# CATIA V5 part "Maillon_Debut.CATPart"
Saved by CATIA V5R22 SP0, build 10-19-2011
Part number: Maillon_debut
Bounding box of the stored display mesh (mm): x -0.4 to 26.6, y -32.303 to 16.847, z -12 to 12
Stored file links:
  C:\Users\achbo\Desktop\BOUCHEMAMA_Achraf_P1-1_Chaine Porte Cables\Maillon_Debut.CATPart
  C:\Program Files\Dassault Systemes\B22\win_b64\startup\materials\French\Catalog.CATMaterial
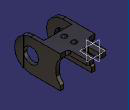
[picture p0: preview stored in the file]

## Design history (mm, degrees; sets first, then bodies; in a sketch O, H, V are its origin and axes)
Body1 (main body), material "Acier"
  Sketch1 on yz-plane, origin (0, 0, 0), H (0, 1, 0), V (0, 0, 1)
    point P1 (1.8468, 12)
    line L1 (1.8468, 12) -> (-20.3032, 12)
    point P2 (-20.3032, 12)
    axis line L2 (84.3362, 0) -> (-201.4699, 0)
    point P3 (84.3362, 0)
    arc A1 centre (-20.3032, 0) radius 12 from (-20.3032, 12) to (-32.3032, 0) ccw
    point P5 (-20.3032, 0)
    point P6 (-32.3032, 0)
    point P7 (-20.3032, -12)
    point P8 (1.8468, -12)
    line L3 (1.8468, -12) -> (-20.3032, -12)
    point P9 (-32.3032, 0)
    arc A2 centre (-20.3032, 0) radius 12 from (-20.3032, -12) to (-32.3032, 0) cw
    line L4 (1.8468, 12) -> (1.8468, 8.802)
    point P11 (1.8468, 8.802)
    point P12 (1.8468, -8.802)
    point P13 (1.8468, -12)
    line L5 (1.8468, -12) -> (1.8468, -8.802)
    arc A3 centre (10.7223, 0) radius 12.5 from (1.8468, 8.802) to (1.8468, -8.802) ccw
    point P15 (0, 6.4251)
    length L1 = 22.15
    radius A1 = 12
    length L4 = 3.198
    radius A3 = 12.5
    horizontal: L1 H, L2 H
    coincidence: P3 H, P5 L2, P6 L2, A3 P15, P15 V, P6 P9, P8 P13
    symmetry: P2 P7 L2, P1 P8 L2, L1 L3 L2, P6 P9 L2, A1 A2 L2, P11 P12 L2, P1 P13 L2, L4 L5 L2
    vertical: L4 V
  Pad1: profile Sketch1, direction (1, 0, 0), length 26.2
  Sketch2 on end face of Pad1, origin (26.2, -24.6429, -1.8283), H (0, 1, 0), V (0, 0, 1)
    point P1 (4.3397, 1.8283)
    reference projected arc E1 centre (4.3397, 1.8283) radius 12 from (4.3397, 13.8283) to (-7.6603, 1.8283) ccw from edge [face of Pad1 from Sketch1.A1 | end face of Pad1]
    concentricity: P1 E1
  Hole1: placed by Sketch2, at (26.2, -20.3032, 0) direction (-1, 0, 0), diameter 11.5, through (limit type 3)
  Sketch3 on end face of Pad1, origin (26.2, 0, 0), H (0, 1, 0), V (0, 0, 1)
    line L1 (-25.8032, 10.6654) -> (-25.8032, -10.6654)
    reference projected point E1 (-32.3032, 0) from vertex [face of Pad1 from Sketch1.A2 | end face of Pad1 | face of Pad1 from Sketch1.A1]
    arc A1 centre (-20.3032, 0) radius 12 from (-25.8032, 10.6654) to (-25.8032, -10.6654) ccw
    point P4 (-32.3032, 0)
    reference projected arc E2 centre (-20.3032, 0) radius 12 from (-32.3032, 0) to (-20.3032, -12) ccw from edge [face of Pad1 from Sketch1.A2 | end face of Pad1]
    reference projected arc E3 centre (-20.3032, 0) radius 12 from (-32.3032, 0) to (-20.3032, -12) ccw from edge [face of Pad1 from Sketch1.A2 | end face of Pad1]
    distance E1 L1 = 6.5
    vertical: L1 V
    coincidence: A1 P4, P4 H, A1 E3
    concentricity: A1 E2
  Pad2: profile Sketch3, direction (1, 0, 0), length 0.4
  Sketch4 on face of Pad1 from Sketch1.L4, origin (0, 1.8468, 0), H (-1, 0, 0), V (0, 0, 1)
    line L1 (-23.6, 8.6) -> (-2.6, 8.6)
    line L2 (-2.6, 8.6) -> (-2.6, -21.2372)
    line L3 (-2.6, -21.2372) -> (-23.6, -21.2372)
    line L4 (-23.6, -21.2372) -> (-23.6, 8.6)
    reference projected line E1 (0, 12) -> (-26.2, 12) from edge [face of Pad1 from Sketch1.L1 | face of Pad1 from Sketch1.L4]
    reference projected line E2 (-26.2, -8.802) -> (-26.2, 8.802) from edge [face of Pad1 from Sketch1.A3 | end face of Pad1]
    reference projected line E3 (0, -8.802) -> (0, 8.802) from edge [start face of Pad1 | face of Pad1 from Sketch1.A3]
    distance L1 E1 = 3.4
    distance L4 E2 = 2.6
    distance L2 E3 = 2.6
    horizontal: L1 H, L3 H
    vertical: L2 V, L4 V
  Pocket1: profile Sketch4, direction (0, -1, 0), through (limit type 3)
  Sketch5 on face of Pad1 from Sketch1.L1, origin (0, 0, 12), H (1, 0, 0), V (0, 1, 0)
    line L1 (2.6, -13.1532) -> (23.6, -13.1532)
    line L2 (23.6, -13.1532) -> (23.6, -30.1162)
    line L3 (23.6, -30.1162) -> (2.6, -30.1162)
    line L4 (2.6, -30.1162) -> (2.6, -13.1532)
    reference projected line E1 (2.6, -32.3032) -> (2.6, -20.3032) from edge [face of Pad2 | face of Pocket1 from Sketch4.L2]
    reference projected line E2 (23.6, -20.3032) -> (23.6, -32.3032) from edge [face of Pad2 | face of Pocket1 from Sketch4.L4]
    reference projected line E3 (0, 1.8468) -> (26.2, 1.8468) from edge [face of Pad1 from Sketch1.L1 | face of Pad1 from Sketch1.L4]
    distance L1 E3 = 15
    horizontal: L1 H, L3 H
    vertical: L2 V, L4 V
    coincidence: E1 L4, L2 E2
  Pocket2: profile Sketch5, direction (0, 0, -1), through (limit type 3)
  Sketch6 on start face of Pad1, origin (0, 0, 0), H (0, -1, 0), V (0, 0, 1)
    point P1 (25.1369, 10.9834)
    line L1 (25.1369, 10.9834) -> (25.1369, -10.9834)
    point P2 (25.1369, -10.9834)
    reference projected arc E1 centre (20.3032, 0) radius 12 from (32.3032, 0) to (20.3032, 12) ccw from edge [start face of Pad1 | face of Pad1 from Sketch1.A1]
    reference projected arc E2 centre (20.3032, 0) radius 12 from (20.3032, -12) to (32.3032, 0) ccw from edge [start face of Pad1 | face of Pad1 from Sketch1.A2]
    arc A1 centre (20.3032, 0) radius 12 from (25.1369, 10.9834) to (25.1369, -10.9834) cw
    point P4 (32.3032, 0)
    reference projected arc E3 centre (20.3032, 0) radius 12 from (20.3032, -12) to (32.3032, 0) ccw from edge [start face of Pad1 | face of Pad1 from Sketch1.A2]
    reference projected arc E4 centre (20.3032, 0) radius 12 from (20.3032, -12) to (32.3032, 0) ccw from edge [start face of Pad1 | face of Pad1 from Sketch1.A2]
    vertical: L1 V
    coincidence: P1 E1, P2 E2, A1 P4, P4 H, A1 E4
    concentricity: A1 E3
  Pad3: profile Sketch6, direction (-1, 0, 0), length 0.4
  Sketch7 on face of Pad1 from Sketch1.L4, origin (0, 1.8468, 0), H (-1, 0, 0), V (0, 0, 1)
    line L1 (-20.2, 12) -> (-6, 12)
    line L2 (-6, 12) -> (-6, 8.6)
    line L3 (-6, 8.6) -> (-20.2, 8.6)
    line L4 (-20.2, 8.6) -> (-20.2, 12)
    reference projected line E1 (0, 8.802) -> (0, 12) from edge [start face of Pad1 | face of Pad1 from Sketch1.L4]
    reference projected line E2 (-26.2, 8.802) -> (-26.2, 12) from edge [face of Pad1 from Sketch1.L4 | end face of Pad1]
    reference intersected line E3 through (0, 8.6) direction (-1, 0) from face of Pocket1 from Sketch4.L1
    reference projected line E4 (0, 12) -> (-26.2, 12) from edge [face of Pad1 from Sketch1.L1 | face of Pad1 from Sketch1.L4]
    distance E1 L2 = 6
    distance L4 E2 = 6
    horizontal: L1 H, L3 H
    vertical: L2 V, L4 V
    coincidence: L3 E3, E4 L1
  Pad4: profile Sketch7, direction (0, 1, 0), length 15
  Sketch8 on end face of Pad4, origin (0, 16.8468, 0), H (-1, 0, 0), V (0, 0, 1)
    line L1 (-15.2, 14.6807) -> (-11, 14.6807)
    line L2 (-11, 14.6807) -> (-11, 5.2571)
    line L3 (-11, 5.2571) -> (-15.2, 5.2571)
    line L4 (-15.2, 5.2571) -> (-15.2, 14.6807)
    reference projected line E1 (-6, 8.6) -> (-6, 12) from edge [face of Pad4 from Sketch7.L2 | end face of Pad4]
    reference projected line E2 (-20.2, 12) -> (-20.2, 8.6) from edge [face of Pad4 from Sketch7.L4 | end face of Pad4]
    distance L2 E1 = 5
    distance L4 E2 = 5
    horizontal: L1 H, L3 H
    vertical: L2 V, L4 V
  Pocket3: profile Sketch8, direction (0, -1, 0), length 10
  Fillet1: radius 1, on edge [face of Pocket3 from Sketch8.L4 | end face of Pocket3]
  Fillet2: radius 1, on edge [face of Pocket3 from Sketch8.L2 | end face of Pocket3]
  Fillet3: radius 2, on edge [face of Pad1 from Sketch1.L4 | face of Pad4 from Sketch7.L4]
  Fillet4: radius 2, on edge [face of Pad1 from Sketch1.L4 | face of Pad4 from Sketch7.L2]
  Sketch9 on face of Pad4, origin (0, 0, 12), H (1, 0, 0), V (0, 1, 0)
    reference projected line E1 (26.2, 1.8468) -> (26.2, -20.3032) from edge [face of Pad1 from Sketch1.L1 | end face of Pad1]
    reference projected line E2 (0, 1.8468) -> (0, -20.3032) from edge [start face of Pad1 | face of Pad1 from Sketch1.L1]
    axis line L1 (13.1, 15.8866) -> (13.1, -31.261)
    reference projected line E3 (26.2, 1.8468) -> (26.2, -20.3032) from edge [face of Pad1 from Sketch1.L1 | end face of Pad1]
    circle A1 centre (13.1, -0.7596) radius 2
    point P3 (13.1, -0.7596)
    circle A2 centre (13.1, -8.2354) radius 2
    point P4 (13.1, -8.2354)
    distance E1 E2 = 26.2 (reference)
    distance E3 L1 = 13.1
    radius A1 = 2
    radius A2 = 2
    vertical: L1 V
    coincidence: P3 L1, P4 L1
  Pocket4: profile Sketch9, direction (0, 0, -1), through (limit type 3)
  Fillet5: radius 1, on edge [face of Pad4 from Sketch7.L2 | end face of Pad4]; edge [end face of Pad4 | face of Pocket3 from Sketch8.L2]; edge [end face of Pad4 | face of Pocket3 from Sketch8.L4]; edge [face of Pad4 from Sketch7.L4 | end face of Pad4]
